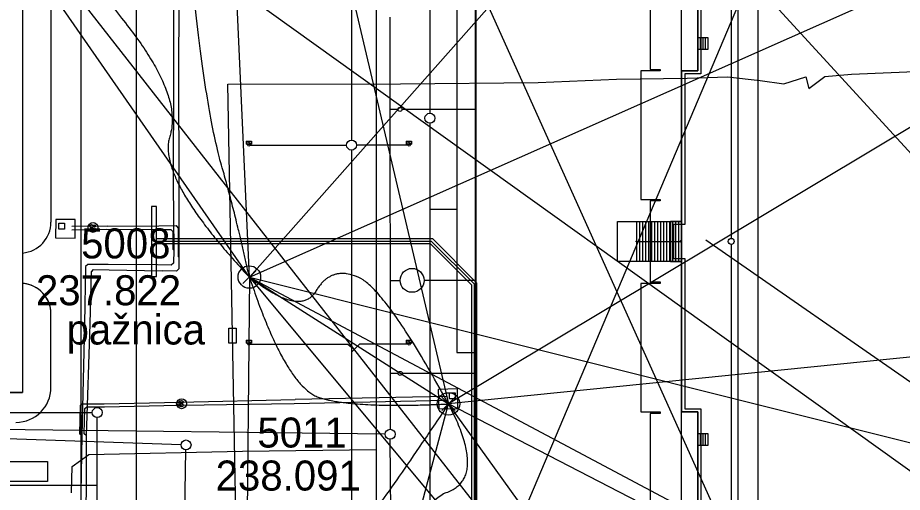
# Model space of a CAD drawing. Extents: x -264090 to -263500, y -1242327 to -1242030.
# Drawn here: x -263959.9 to -263871.6, y -1242189.5 to -1242142 of the extents above; entities that cross this region are included whole.
import ezdxf

# ---------------------------------------------------------------- set-up
doc = ezdxf.new("R2010")
doc.units = 0
for name, color, linetype in [('KFA_KOORD_SIT_a_IS_SEDA', 7, 'Continuous'), ('KFA_ZVS_BOD_CISLO', 7, 'Continuous'), ('KFA_ZVS_BOD_SYMBOL', 7, 'Continuous'), ('KFA_ZVS_BOD_VYSKA', 7, 'Continuous'), ('KFA_ZVS_NIVELACIA', 7, 'Continuous'), ('KFA_ZVS_POPIS', 7, 'Continuous'), ('KFA_ZVS_SMERY_A_DLZKY', 7, 'Continuous')]:
    doc.layers.add(name, color=color, linetype=linetype)

msp = doc.modelspace()

# ---------------------------------------------------------------- linework, layer by layer
at = {"layer": 'KFA_KOORD_SIT_a_IS_SEDA'}
for p, q in [((-263959.468, -1242059.534), (-263959.468, -1242179.482)), ((-263924.143, -1242082.64), (-263924.143, -1242185.14)), ((-263948.093, -1242087.901), (-263948.093, -1242241.458)), ((-263953.617, -1242244.458), (-263953.617, -1242093.307)), ((-263926.593, -1242107.902), (-263926.593, -1242154.252)), ((-263926.593, -1242107.902), (-263926.593, -1242154.252)), ((-263918.855, -1242107.583), (-263918.765, -1242151.564)), ((-263888.673, -1242108.177), (-263888.673, -1242164.087)), ((-263896.768, -1242125.432), (-263896.768, -1242147.182)), ((-263956.618, -1242127.418), (-263956.618, -1242162.449)), ((-263914.218, -1242196.332), (-263914.218, -1242132.432)), ((-263944.369, -1242139.25), (-263944.386, -1242147.884)), ((-263943.839, -1242139.271), (-263943.869, -1242147.889)), ((-263922.763, -1242141.975), (-263922.734, -1242183.174)), ((-263892.018, -1242143.983), (-263891.018, -1242143.983)), ((-263891.768, -1242143.983), (-263891.768, -1242145.181)), ((-263891.518, -1242143.983), (-263891.518, -1242145.181)), ((-263891.268, -1242143.983), (-263891.268, -1242145.181)), ((-263891.018, -1242143.983), (-263891.018, -1242145.181)), ((-263891.018, -1242145.181), (-263892.018, -1242145.181)), ((-263896.768, -1242147.182), (-263895.768, -1242147.182)), ((-263895.768, -1242147.182), (-263895.768, -1242147.332)), ((-263876.651, -1242147.671), (-263865.322, -1242147.201)), ((-263944.386, -1242147.884), (-263944.412, -1242158.664)), ((-263943.869, -1242147.889), (-263943.853, -1242158.652)), ((-263907.955, -1242148.477), (-263900.133, -1242148.17)), ((-263900.133, -1242148.17), (-263893.085, -1242148.072)), ((-263895.768, -1242147.332), (-263897.693, -1242147.332)), ((-263897.693, -1242147.332), (-263897.693, -1242160.182)), ((-263893.085, -1242148.072), (-263889.033, -1242147.931)), ((-263889.033, -1242147.931), (-263885.793, -1242148.286)), ((-263883.413, -1242148.635), (-263881.214, -1242147.927)), ((-263881.214, -1242147.927), (-263880.905, -1242149.089)), ((-263880.905, -1242149.089), (-263879.323, -1242147.877)), ((-263879.323, -1242147.877), (-263876.651, -1242147.671)), ((-263938.95, -1242148.666), (-263921.69, -1242148.626)), ((-263937.993, -1242200.068), (-263938.95, -1242148.666)), ((-263921.69, -1242148.626), (-263907.955, -1242148.477)), ((-263885.793, -1242148.286), (-263883.413, -1242148.635)), ((-263921.957, -1242151.182), (-263922.757, -1242151.182)), ((-263917.093, -1242151.182), (-263921.557, -1242151.182)), ((-263914.143, -1242151.182), (-263917.093, -1242151.182)), ((-263918.764, -1242152.564), (-263918.757, -1242196.225)), ((-263937.093, -1242154.652), (-263937.093, -1242154.362)), ((-263937.093, -1242154.362), (-263936.593, -1242154.362)), ((-263936.593, -1242154.652), (-263937.093, -1242154.362)), ((-263936.593, -1242154.652), (-263937.093, -1242154.362)), ((-263937.093, -1242154.362), (-263937.093, -1242154.652)), ((-263936.593, -1242154.362), (-263936.593, -1242154.652)), ((-263921.093, -1242154.652), (-263921.093, -1242154.362)), ((-263921.093, -1242154.362), (-263920.593, -1242154.362)), ((-263920.593, -1242154.652), (-263921.093, -1242154.362)), ((-263920.593, -1242154.652), (-263921.093, -1242154.362)), ((-263921.093, -1242154.362), (-263921.093, -1242154.652)), ((-263920.593, -1242154.362), (-263920.593, -1242154.652)), ((-263936.593, -1242154.652), (-263937.093, -1242154.652)), ((-263937.093, -1242154.652), (-263936.593, -1242154.652)), ((-263936.743, -1242154.752), (-263927.093, -1242154.752)), ((-263926.593, -1242155.252), (-263926.593, -1242204.252)), ((-263920.944, -1242154.752), (-263926.093, -1242154.752)), ((-263920.593, -1242154.652), (-263921.093, -1242154.652)), ((-263921.093, -1242154.652), (-263920.593, -1242154.652)), ((-263944.412, -1242158.664), (-263944.352, -1242165.249)), ((-263943.853, -1242158.652), (-263943.849, -1242165.958)), ((-263897.693, -1242160.182), (-263895.768, -1242160.182)), ((-263895.768, -1242160.332), (-263896.768, -1242160.332)), ((-263896.768, -1242160.332), (-263896.768, -1242168.432)), ((-263895.768, -1242160.182), (-263895.768, -1242160.332)), ((-263916.093, -1242161.182), (-263918.763, -1242161.182)), ((-263956.13, -1242162.18), (-263956.156, -1242164.04)), ((-263954.192, -1242162.207), (-263956.13, -1242162.18)), ((-263954.218, -1242164.067), (-263954.192, -1242162.207)), ((-263955.831, -1242163.152), (-263955.831, -1242162.573)), ((-263955.831, -1242162.573), (-263955.28, -1242162.573)), ((-263955.28, -1242163.152), (-263955.831, -1242163.152)), ((-263955.28, -1242162.573), (-263955.28, -1242163.152)), ((-263951.019, -1242162.854), (-263954.543, -1242162.888)), ((-263951.079, -1242163.196), (-263954.539, -1242163.255)), ((-263945.899, -1242163.231), (-263951.079, -1242163.196)), ((-263951.019, -1242162.854), (-263945.83, -1242162.832)), ((-263944.614, -1242163.211), (-263945.899, -1242163.231)), ((-263945.83, -1242162.832), (-263944.071, -1242162.801)), ((-263944.447, -1242163.393), (-263944.614, -1242163.211)), ((-263943.916, -1242163.012), (-263944.071, -1242162.801)), ((-263943.914, -1242163.012), (-263943.913, -1242165.895)), ((-263898.118, -1242162.382), (-263898.118, -1242166.382)), ((-263897.818, -1242162.382), (-263897.818, -1242166.382)), ((-263897.518, -1242162.382), (-263897.518, -1242166.382)), ((-263897.218, -1242162.382), (-263897.218, -1242166.382)), ((-263896.918, -1242162.382), (-263896.918, -1242166.382)), ((-263896.618, -1242162.382), (-263896.618, -1242166.382)), ((-263896.318, -1242162.382), (-263896.318, -1242166.382)), ((-263896.018, -1242162.382), (-263896.018, -1242166.382)), ((-263895.718, -1242162.382), (-263895.718, -1242166.382)), ((-263895.418, -1242162.382), (-263895.418, -1242166.382)), ((-263895.118, -1242162.382), (-263895.118, -1242166.382)), ((-263894.818, -1242162.382), (-263894.818, -1242166.382)), ((-263894.518, -1242162.382), (-263894.518, -1242166.382)), ((-263894.218, -1242162.382), (-263894.218, -1242166.382)), ((-263893.918, -1242162.382), (-263893.918, -1242166.382)), ((-263893.618, -1242162.382), (-263893.618, -1242166.382)), ((-263956.156, -1242164.04), (-263954.218, -1242164.067)), ((-263944.447, -1242163.393), (-263944.442, -1242165.164)), ((-263918.489, -1242164.132), (-263946.093, -1242164.132)), ((-263918.593, -1242164.382), (-263946.093, -1242164.382)), ((-263918.696, -1242164.632), (-263946.093, -1242164.632)), ((-263898.118, -1242164.382), (-263893.618, -1242164.382)), ((-263893.618, -1242164.382), (-263893.721, -1242164.274)), ((-263893.618, -1242164.382), (-263893.721, -1242164.491)), ((-263891.208, -1242164.228), (-263859.802, -1242186.093)), ((-263888.673, -1242164.687), (-263888.673, -1242220.396)), ((-263959.468, -1242165.549), (-263959.468, -1242165.549)), ((-263944.442, -1242165.164), (-263944.352, -1242165.249)), ((-263944.442, -1242165.164), (-263944.442, -1242165.164)), ((-263944.352, -1242165.249), (-263944.379, -1242166.564)), ((-263952.942, -1242166.698), (-263953.167, -1242166.907)), ((-263950.896, -1242166.694), (-263952.942, -1242166.698)), ((-263945.968, -1242166.741), (-263950.896, -1242166.694)), ((-263944.61, -1242166.777), (-263945.968, -1242166.741)), ((-263944.379, -1242166.564), (-263944.61, -1242166.777)), ((-263943.913, -1242165.895), (-263943.849, -1242165.958)), ((-263943.913, -1242165.895), (-263943.913, -1242165.895)), ((-263943.849, -1242165.958), (-263943.861, -1242167.143)), ((-263953.167, -1242166.907), (-263953.276, -1242172.621)), ((-263952.715, -1242172.612), (-263952.57, -1242167.416)), ((-263952.57, -1242167.416), (-263952.361, -1242167.2)), ((-263952.361, -1242167.2), (-263950.803, -1242167.244)), ((-263950.803, -1242167.244), (-263945.525, -1242167.325)), ((-263944.087, -1242167.347), (-263945.525, -1242167.325)), ((-263943.861, -1242167.143), (-263944.087, -1242167.347)), ((-263922.745, -1242168.282), (-263921.745, -1242168.282)), ((-263914.143, -1242168.282), (-263919.355, -1242168.282)), ((-263896.768, -1242168.432), (-263895.768, -1242168.432)), ((-263895.768, -1242168.432), (-263895.768, -1242168.582)), ((-263959.467, -1242168.582), (-263959.467, -1242168.582)), ((-263895.768, -1242168.582), (-263897.693, -1242168.582)), ((-263897.693, -1242168.582), (-263897.693, -1242181.432)), ((-263956.618, -1242178.982), (-263956.618, -1242171.645)), ((-263953.276, -1242172.621), (-263953.528, -1242183.799)), ((-263953.067, -1242183.845), (-263952.715, -1242172.612)), ((-263938.869, -1242173.048), (-263938.119, -1242173.046)), ((-263938.863, -1242174.548), (-263938.869, -1242173.048)), ((-263938.119, -1242173.046), (-263938.113, -1242174.546)), ((-263938.113, -1242174.546), (-263938.863, -1242174.548)), ((-263938.863, -1242174.548), (-263938.863, -1242174.548)), ((-263937.093, -1242174.553), (-263937.093, -1242174.263)), ((-263937.093, -1242174.263), (-263936.593, -1242174.263)), ((-263936.593, -1242174.553), (-263937.093, -1242174.263)), ((-263936.593, -1242174.553), (-263937.093, -1242174.263)), ((-263937.093, -1242174.263), (-263937.093, -1242174.553)), ((-263936.593, -1242174.553), (-263937.093, -1242174.553)), ((-263937.093, -1242174.553), (-263936.593, -1242174.553)), ((-263936.743, -1242174.653), (-263926.953, -1242174.653)), ((-263936.593, -1242174.263), (-263936.593, -1242174.553)), ((-263926.953, -1242174.653), (-263926.593, -1242174.978)), ((-263925.798, -1242174.653), (-263926.593, -1242175.448)), ((-263920.944, -1242174.653), (-263925.798, -1242174.653)), ((-263921.093, -1242174.553), (-263921.093, -1242174.263)), ((-263921.093, -1242174.263), (-263920.593, -1242174.263)), ((-263920.593, -1242174.553), (-263921.093, -1242174.263)), ((-263920.593, -1242174.553), (-263921.093, -1242174.263)), ((-263921.093, -1242174.263), (-263921.093, -1242174.553)), ((-263920.593, -1242174.553), (-263921.093, -1242174.553)), ((-263921.093, -1242174.553), (-263920.593, -1242174.553)), ((-263920.593, -1242174.263), (-263920.593, -1242174.553)), ((-263921.938, -1242177.582), (-263922.738, -1242177.582)), ((-263915.293, -1242177.582), (-263921.538, -1242177.582)), ((-263914.143, -1242177.582), (-263915.293, -1242177.582)), ((-263956.618, -1242178.982), (-263956.618, -1242178.982)), ((-264089.658, -1242179.482), (-263959.468, -1242179.482)), ((-263959.468, -1242179.482), (-264089.658, -1242179.482)), ((-263959.468, -1242179.482), (-264077.23, -1242179.482)), ((-263917.138, -1242179.908), (-263932.226, -1242180.187)), ((-263916.007, -1242179.139), (-263917.932, -1242179.184)), ((-263917.932, -1242179.184), (-263917.886, -1242181.133)), ((-263916.803, -1242180.116), (-263916.803, -1242179.537)), ((-263916.803, -1242179.537), (-263916.252, -1242179.537)), ((-263916.252, -1242179.537), (-263916.252, -1242180.116)), ((-263915.961, -1242181.088), (-263916.007, -1242179.139)), ((-263953.71, -1242180.8), (-263953.774, -1242183.629)), ((-263953.71, -1242180.8), (-263953.518, -1242180.617)), ((-263953.518, -1242180.617), (-263951.311, -1242180.614)), ((-263951.311, -1242180.614), (-263943.779, -1242180.456)), ((-263951.265, -1242180.941), (-263943.848, -1242180.778)), ((-263943.848, -1242180.778), (-263943.567, -1242180.776)), ((-263943.779, -1242180.456), (-263932.226, -1242180.187)), ((-263943.567, -1242180.776), (-263932.313, -1242180.597)), ((-263932.313, -1242180.597), (-263917.138, -1242180.263)), ((-263916.252, -1242180.116), (-263916.803, -1242180.116)), ((-263963.161, -1242181.5), (-263952.5, -1242181.5)), ((-263953.31, -1242183.629), (-263953.231, -1242181.09)), ((-263953.231, -1242181.09), (-263953.049, -1242180.917)), ((-263953.049, -1242180.917), (-263951.265, -1242180.941)), ((-263917.886, -1242181.133), (-263915.961, -1242181.088)), ((-263897.693, -1242181.432), (-263895.768, -1242181.432)), ((-263895.768, -1242181.582), (-263896.768, -1242181.582)), ((-263896.768, -1242181.582), (-263896.768, -1242203.332)), ((-263895.768, -1242181.432), (-263895.768, -1242181.582)), ((-263952, -1242222.527), (-263952, -1242182)), ((-263923.234, -1242183.668), (-263965.273, -1242183.165)), ((-263943.628, -1242184.728), (-263963.161, -1242184.046)), ((-263953.528, -1242183.799), (-263953.774, -1242183.629)), ((-263953.528, -1242183.799), (-263953.63, -1242189.514)), ((-263953.067, -1242183.845), (-263953.31, -1242183.629)), ((-263953.083, -1242189.456), (-263953.067, -1242183.845)), ((-263922.479, -1242221.753), (-263922.731, -1242184.174)), ((-263892.018, -1242183.583), (-263891.018, -1242183.583)), ((-263891.768, -1242183.583), (-263891.768, -1242184.781)), ((-263891.518, -1242183.583), (-263891.518, -1242184.781)), ((-263891.268, -1242183.583), (-263891.268, -1242184.781)), ((-263891.018, -1242183.583), (-263891.018, -1242184.781)), ((-263943.946, -1242236.311), (-263943.136, -1242185.245)), ((-263937.488, -1242185.363), (-263924.143, -1242185.192)), ((-263924.143, -1242185.14), (-263924.143, -1242250.14)), ((-263891.018, -1242184.781), (-263892.018, -1242184.781)), ((-263954.509, -1242186.913), (-263952.832, -1242185.692)), ((-263952.832, -1242185.692), (-263937.488, -1242185.363)), ((-263954.57, -1242189.535), (-263954.509, -1242186.913)), ((-263961.868, -1242188.772), (-263952, -1242188.772)), ((-263953.266, -1242197.902), (-263953.083, -1242189.456))]:
    msp.add_line(p, q, dxfattribs=at)
for points in [[(-263794.893, -1242227.382), (-263808.968, -1242241.457), (-263894.968, -1242241.457), (-263909.043, -1242227.382), (-263909.043, -1242196.333), (-263914.143, -1242196.333), (-263914.143, -1242132.433), (-263909.043, -1242132.433), (-263909.043, -1242101.382), (-263894.968, -1242087.307), (-263808.968, -1242087.307), (-263794.893, -1242101.382), (-263794.893, -1242227.382)], [(-263816.02, -1242224.432), (-263887.916, -1242224.432), (-263888.26, -1242224.088), (-263889.254, -1242226.488), (-263890.391, -1242225.351), (-263894.351, -1242229.311), (-263896.896, -1242226.765), (-263892.937, -1242222.806), (-263894.073, -1242221.669), (-263891.673, -1242220.675), (-263892.018, -1242220.33), (-263892.018, -1242181.432), (-263893.618, -1242181.432), (-263893.618, -1242147.332), (-263892.018, -1242147.332), (-263892.018, -1242108.434)], [(-263918.696, -1242164.632), (-263914.6, -1242168.728), (-263914.6, -1242199.693), (-263910.211, -1242204.082), (-263891.768, -1242204.082)], [(-263918.593, -1242164.382), (-263914.35, -1242168.625), (-263914.35, -1242199.59), (-263910.108, -1242203.832), (-263891.768, -1242203.832)], [(-263918.489, -1242164.132), (-263914.1, -1242168.521), (-263914.1, -1242199.486), (-263910.004, -1242203.582), (-263891.768, -1242203.582)], [(-263956.618, -1242178.982), (-263956.618, -1242171.626), (-263956.64, -1242171.257), (-263956.707, -1242170.894), (-263956.87, -1242170.411), (-263957.158, -1242169.893), (-263957.435, -1242169.549), (-263957.705, -1242169.291), (-263958.077, -1242169.024), (-263958.45, -1242168.829), (-263958.842, -1242168.69), (-263959.056, -1242168.638), (-263959.273, -1242168.601), (-263959.468, -1242168.582)]]:
    msp.add_lwpolyline(points, dxfattribs=at)
for points in [[(-263816.02, -1242224.432), (-263811.918, -1242220.33), (-263811.918, -1242108.434), (-263816.02, -1242104.332), (-263887.916, -1242104.332), (-263892.018, -1242108.434), (-263892.018, -1242147.332), (-263893.618, -1242147.332), (-263893.618, -1242162.382), (-263894.718, -1242162.382), (-263894.718, -1242166.382), (-263893.618, -1242166.382), (-263893.618, -1242181.432), (-263892.018, -1242181.432), (-263892.018, -1242220.33), (-263887.916, -1242224.432)], [(-263816.144, -1242224.132), (-263812.218, -1242220.206), (-263812.218, -1242108.558), (-263816.144, -1242104.632), (-263887.792, -1242104.632), (-263891.718, -1242108.558), (-263891.718, -1242147.632), (-263893.318, -1242147.632), (-263893.318, -1242162.682), (-263894.418, -1242162.682), (-263894.418, -1242166.082), (-263893.318, -1242166.082), (-263893.318, -1242181.132), (-263891.718, -1242181.132), (-263891.718, -1242220.206), (-263887.792, -1242224.132)], [(-263887.968, -1242108.434), (-263815.968, -1242108.434), (-263815.968, -1242220.33), (-263887.968, -1242220.33)], [(-263885.968, -1242111.882), (-263817.968, -1242111.882), (-263817.968, -1242216.882), (-263885.968, -1242216.882)], [(-263893.618, -1242118.282), (-263916.093, -1242118.282), (-263916.093, -1242175.482), (-263914.293, -1242175.482), (-263914.293, -1242210.482), (-263893.618, -1242210.482), (-263893.618, -1242166.382), (-263900.043, -1242166.382), (-263900.043, -1242162.382), (-263893.618, -1242162.382)], [(-263946.093, -1242167.882), (-263946.093, -1242160.882), (-263946.593, -1242160.882), (-263946.593, -1242167.882)], [(-263966.968, -1242186.382), (-263956.968, -1242186.382), (-263956.968, -1242188.382), (-263966.968, -1242188.382)]]:
    msp.add_lwpolyline(points, close=True, dxfattribs=at)
for centre, radius in [((-263921.757, -1242151.182), 0.2), ((-263918.764, -1242152.064), 0.5), ((-263926.593, -1242154.752), 0.5), ((-263936.843, -1242154.752), 0.1), ((-263920.844, -1242154.752), 0.1), ((-263952.413, -1242162.992), 0.487), ((-263952.568, -1242162.867), 0.164), ((-263952.568, -1242163.22), 0.164), ((-263952.284, -1242162.851), 0.122), ((-263952.284, -1242163.187), 0.122), ((-263888.673, -1242164.387), 0.3), ((-263898.118, -1242164.382), 0.05), ((-263920.55, -1242168.282), 1.195), ((-263936.843, -1242174.653), 0.1), ((-263920.844, -1242174.653), 0.1), ((-263921.738, -1242177.582), 0.2), ((-263943.568, -1242180.617), 0.496), ((-263943.848, -1242180.461), 0.122), ((-263943.848, -1242180.778), 0.122), ((-263943.567, -1242180.445), 0.164), ((-263943.567, -1242180.776), 0.164), ((-263952, -1242181.5), 0.5), ((-263922.734, -1242183.674), 0.5), ((-263943.128, -1242184.745), 0.5)]:
    msp.add_circle(centre, radius, dxfattribs=at)
for centre, radius, start, end in [((-263959.738, -1242162.441), 3.12, 274.96374, 359.8482), ((-263959.668, -1242171.626), 3.05, 359.64411, 86.21555), ((-263960.118, -1242178.982), 3.5, 270, 0)]:
    msp.add_arc(centre, radius, start, end, dxfattribs=at)
at = {"layer": 'KFA_ZVS_BOD_SYMBOL'}
for p, q in [((-263937.465, -1242168.61), (-263936.139, -1242167.284)), ((-263936.139, -1242168.61), (-263937.465, -1242167.284)), ((-263917.567, -1242181.304), (-263916.241, -1242179.978)), ((-263916.241, -1242181.304), (-263917.567, -1242179.978))]:
    msp.add_line(p, q, dxfattribs=at)
for centre in [(-263936.802, -1242167.947), (-263916.904, -1242180.641)]:
    msp.add_circle(centre, 1.125, dxfattribs=at)
at = {"layer": 'KFA_ZVS_NIVELACIA'}
for points in [[(-263940.788, -1242078.938), (-263950.124, -1242102.026), (-263955.973, -1242123.929), (-263955.973, -1242134.13), (-263943.376, -1242149.689), (-263946.118, -1242158.004), (-263936.802, -1242167.947)], [(-263936.802, -1242167.947), (-263938.18, -1242161.645), (-263941.069, -1242151.603), (-263943.851, -1242126.263), (-263950.707, -1242125.062), (-263946.422, -1242113.061), (-263941.281, -1242104.232), (-263940.788, -1242078.938)], [(-263916.904, -1242180.641), (-263923.135, -1242169.24), (-263928.619, -1242166.754), (-263931.704, -1242171.983), (-263936.802, -1242167.947)], [(-263936.802, -1242167.947), (-263933.173, -1242178.942), (-263926.403, -1242181.085), (-263916.904, -1242180.641)], [(-263916.904, -1242180.641), (-263925.798, -1242193.852), (-263930.312, -1242198.613), (-263934.768, -1242209.95), (-263940.766, -1242217.665), (-263943.387, -1242229.195), (-263938.661, -1242239.053), (-263943.261, -1242249.943), (-263937.6, -1242258.211)], [(-263937.6, -1242258.211), (-263940.179, -1242249.78), (-263938.22, -1242238.563), (-263938.948, -1242223.279), (-263930.232, -1242215.099), (-263920.849, -1242190.894), (-263913.063, -1242187.955), (-263916.904, -1242180.641)]]:
    msp.add_open_spline(points, degree=2, dxfattribs=at)
at = {"layer": 'KFA_ZVS_SMERY_A_DLZKY'}
for p, q in [((-263937.6, -1242258.211), (-263845.523, -1242040.303)), ((-263936.802, -1242167.947), (-263854.005, -1242074.334)), ((-263936.802, -1242167.947), (-263940.788, -1242078.938)), ((-263786.209, -1242248.09), (-263940.788, -1242078.938)), ((-263858.267, -1242262.294), (-263940.788, -1242078.938)), ((-263940.788, -1242078.938), (-263916.904, -1242180.641)), ((-263936.802, -1242167.947), (-263779.167, -1242098.021)), ((-263779.167, -1242098.021), (-263916.904, -1242180.641)), ((-263936.802, -1242167.947), (-263975.491, -1242112.207)), ((-263786.209, -1242248.09), (-263975.491, -1242112.207)), ((-263858.267, -1242262.294), (-263975.491, -1242112.207)), ((-263768.002, -1242165.53), (-263916.904, -1242180.641)), ((-263936.802, -1242167.947), (-263937.6, -1242258.211)), ((-263936.802, -1242167.947), (-263916.904, -1242180.641)), ((-263936.802, -1242167.947), (-263858.267, -1242262.294)), ((-263936.802, -1242167.947), (-263786.209, -1242248.09)), ((-263936.802, -1242167.947), (-263719.503, -1242222.506)), ((-263937.6, -1242258.211), (-263916.904, -1242180.641)), ((-263786.209, -1242248.09), (-263916.904, -1242180.641)), ((-263858.267, -1242262.294), (-263916.904, -1242180.641))]:
    msp.add_line(p, q, dxfattribs=at)

# ---------------------------------------------------------------- texts
at = {"layer": 'KFA_ZVS_BOD_CISLO'}
for s, p in [('5008', (-263953.608, -1242166.086)), ('5011', (-263936.001, -1242185.001))]:
    msp.add_text(s, height=3, dxfattribs=at).set_placement(p)
at = {"layer": 'KFA_ZVS_BOD_VYSKA'}
for s, p in [('237.822', (-263958.118, -1242170.77)), ('238.091', (-263940.17, -1242189.301))]:
    msp.add_text(s, height=3, dxfattribs=at).set_placement(p)
at = {"layer": 'KFA_ZVS_POPIS'}
msp.add_text('pažnica', height=3, dxfattribs=at).set_placement((-263955.059, -1242174.695))

doc.saveas('drawing.dxf')
